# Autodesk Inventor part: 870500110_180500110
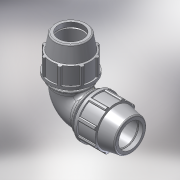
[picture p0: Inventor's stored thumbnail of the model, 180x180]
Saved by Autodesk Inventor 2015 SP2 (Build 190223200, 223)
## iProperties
Created: 2017-02
Part Number: 870500110_180500110
Material: PVC-Piping
Description: PLASSON 90° ELBOW 110-110
Document SubType Name: Modeling
Designer: KIM
Mass: 92.6774 g
Surface Area: 199.44 cm^2
Volume: 66.1981 cm^3
Density: 1.4 g/cm^3
Appearance: Smooth - White
Author: KIM
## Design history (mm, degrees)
derived "87050.ipt"
feature "Solid1::87050.ipt"
tag "TaggingFeature1"
body "Solid1"
other parameters: "d4" = 24.5, "d5" = 73.5, "d7" = 181, "d9" = 42, "d11" = 11.76, "d13" = 120 deg, "d14" = 143, "d15" = 10 deg, "d16" = 166.52, "d18" = 5.5, "d19" = 35 deg, "d20" = 17.5 deg, "d21" = 168.33, "d23" = 0, "d25" = 360 deg, "d27" = 3.62, "d33" = 2.2, "d42" = 99.96, "d43" = 5.43, "d46" = 3.3, "d51" = 294, "d59" = 90 deg, "d63" = 196, "d64" = 99, "d67" = 135.75, "d68" = 21.168, "d70" = 90 deg, "d71" = 16.5, "d72" = 12.06667, "d73" = 0, "d75" = 90 deg, "d77" = 163.1896, "d78" = 7.056, "E_" = 181, "A_" = 294, "l_" = 196
